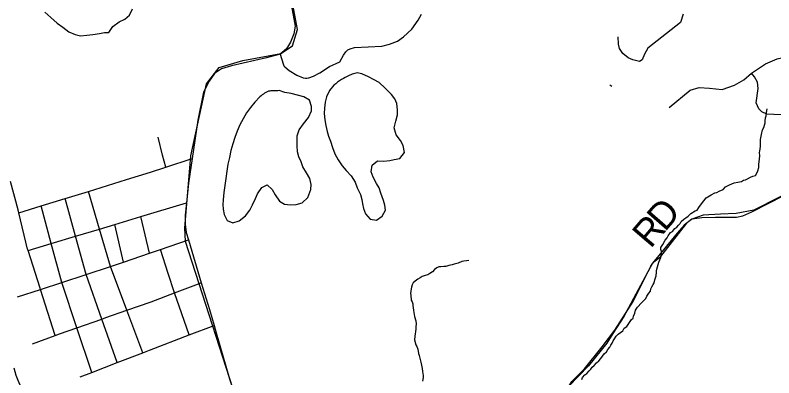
# Model space of a CAD drawing. Extents: x 0 to 34, y 0 to 22.
# Drawn here: x 2.523 to 3.323, y 15.477 to 15.86 of the extents above; entities that cross this region are included whole.
import ezdxf

# ---------------------------------------------------------------- set-up
doc = ezdxf.new("R2010")
doc.units = 0
for name, color, linetype in [('GM_X_City_Street', 7, 'Continuous'), ('GM_X_County_Road', 7, 'Continuous'), ('GM_X_County_Road_Text', 7, 'Continuous'), ('GM_X_Major_River', 7, 'Continuous'), ('GM_X_Minor_Lake', 7, 'Continuous'), ('GM_X_Minor_River', 7, 'Continuous'), ('GM_X_Rail_Line', 7, 'Continuous'), ('GM_X_Township_Road', 7, 'Continuous'), ('GM_X_US_Route', 7, 'Continuous')]:
    doc.layers.add(name, color=color, linetype=linetype)

msp = doc.modelspace()

# ---------------------------------------------------------------- linework, layer by layer
at = {"layer": 'GM_X_City_Street'}
for p, q in [((2.66455, 15.60886), (2.65535, 15.64744)), ((2.63694, 15.59946), (2.62776, 15.63911))]:
    msp.add_line(p, q, dxfattribs=at)
for points in [[(2.68156, 15.69953), (2.67833, 15.71215), (2.67348, 15.73109)], [(2.52675, 15.65143), (2.55011, 15.65857), (2.57554, 15.66634), (2.60022, 15.67389), (2.64032, 15.68642), (2.66539, 15.69425), (2.68156, 15.69953), (2.70934, 15.70857)], [(2.5649, 15.52203), (2.54956, 15.57061), (2.54918, 15.5718), (2.53648, 15.61153), (2.53597, 15.61313), (2.52675, 15.65143), (2.52598, 15.6546), (2.51791, 15.68449)], [(2.65747, 15.50379), (2.64059, 15.54861), (2.62319, 15.59479), (2.61173, 15.63427), (2.60022, 15.67389)], [(2.63037, 15.49334), (2.61415, 15.53936), (2.59758, 15.58638), (2.58649, 15.62664), (2.57554, 15.66634)], [(2.53648, 15.61153), (2.56082, 15.61888), (2.58649, 15.62664), (2.61173, 15.63427), (2.62776, 15.63911), (2.65535, 15.64744), (2.70346, 15.66198)], [(2.60372, 15.48307), (2.5879, 15.53018), (2.57187, 15.57794), (2.56082, 15.61888), (2.55011, 15.65857)], [(2.52537, 15.56267), (2.54956, 15.57061), (2.55046, 15.57091), (2.57187, 15.57794), (2.59758, 15.58638), (2.62319, 15.59479), (2.63694, 15.59946), (2.66455, 15.60886), (2.676, 15.61275), (2.70543, 15.62276)], [(2.7064, 15.52255), (2.69073, 15.56686), (2.68409, 15.58753), (2.676, 15.61275)], [(2.54111, 15.51316), (2.5649, 15.52203), (2.56949, 15.52373), (2.5879, 15.53018), (2.61415, 15.53936), (2.61832, 15.54082), (2.64059, 15.54861), (2.6662, 15.55757), (2.69073, 15.56686), (2.7191, 15.5776)], [(2.59135, 15.4783), (2.60372, 15.48307), (2.63037, 15.49334), (2.65747, 15.50379), (2.6643, 15.50642), (2.7064, 15.52255), (2.7325, 15.53255)]]:
    msp.add_lwpolyline(points, dxfattribs=at)
at = {"layer": 'GM_X_County_Road'}
for points in [[(2.80226, 15.81868), (2.80525, 15.80862), (2.80625, 15.8064), (2.80731, 15.80516), (2.81159, 15.80161), (2.81975, 15.79643), (2.82633, 15.79387), (2.82901, 15.79355), (2.8305, 15.79352), (2.8324, 15.79378), (2.83734, 15.79542), (2.84421, 15.79892), (2.85416, 15.80559), (2.86522, 15.81074), (2.86892, 15.8177), (2.87148, 15.82118), (2.87375, 15.82332), (2.87588, 15.82445), (2.88059, 15.82568), (2.90959, 15.82715), (2.91739, 15.82912), (2.92596, 15.8324), (2.93246, 15.83704), (2.9411, 15.84507), (2.94779, 15.85468), (2.9511, 15.8608)], [(3.01015, 15.37328), (3.01126, 15.3743), (3.02228, 15.38409), (3.08942, 15.44382), (3.09512, 15.45085), (3.10361, 15.46292), (3.10979, 15.47334), (3.12306, 15.48697), (3.14191, 15.5101), (3.1553, 15.52771), (3.17436, 15.55784), (3.19325, 15.59517), (3.19641, 15.59962), (3.20358, 15.60529), (3.21361, 15.61787), (3.23092, 15.64029), (3.23367, 15.64299), (3.23674, 15.64485), (3.24682, 15.64627), (3.26123, 15.6468), (3.28338, 15.64672), (3.29024, 15.64823), (3.29964, 15.65231), (3.36693, 15.68691)]]:
    msp.add_lwpolyline(points, dxfattribs=at)
at = {"layer": 'GM_X_Major_River'}
for points in [[(2.55404, 15.86283), (2.56036, 15.8572), (2.56706, 15.85156), (2.57303, 15.84707), (2.57937, 15.8422), (2.58594, 15.83941), (2.5916, 15.83815), (2.59823, 15.83859), (2.60469, 15.83941), (2.61191, 15.84059), (2.61685, 15.84163), (2.62158, 15.84172), (2.62568, 15.84771), (2.63241, 15.85289), (2.63834, 15.85562), (2.64353, 15.85969), (2.64651, 15.86665)], [(2.57421, 15.3616), (2.5689, 15.37081), (2.56618, 15.37637), (2.56271, 15.3827), (2.5611, 15.38748), (2.55855, 15.39265), (2.5562, 15.39821), (2.55311, 15.40434), (2.54982, 15.41029), (2.54766, 15.41603), (2.54606, 15.4208), (2.54393, 15.42787), (2.54234, 15.43359), (2.5402, 15.44028), (2.53784, 15.44526), (2.53479, 15.45386), (2.53154, 15.46133), (2.52612, 15.47434), (2.52377, 15.47989), (2.52165, 15.48734)]]:
    msp.add_lwpolyline(points, dxfattribs=at)
at = {"layer": 'GM_X_Minor_Lake'}
for points in [[(2.85893, 15.78593), (2.85429, 15.78031), (2.85095, 15.77354), (2.84954, 15.76806), (2.84887, 15.76181), (2.84858, 15.75594), (2.84923, 15.74929), (2.85028, 15.74358), (2.8517, 15.7371), (2.85313, 15.73215), (2.85514, 15.72681), (2.85731, 15.72032), (2.86005, 15.71364), (2.86336, 15.70713), (2.86762, 15.70081), (2.87191, 15.69599), (2.87694, 15.69041), (2.8812, 15.6837), (2.88357, 15.67759), (2.88688, 15.67071), (2.8885, 15.66556), (2.889, 15.66081), (2.89005, 15.65586), (2.89205, 15.65033), (2.89709, 15.64475), (2.90371, 15.64369), (2.90966, 15.64777), (2.91318, 15.65416), (2.91251, 15.65949), (2.91126, 15.66444), (2.90834, 15.67207), (2.90653, 15.6776), (2.90376, 15.68239), (2.90026, 15.6889), (2.89808, 15.69462), (2.89933, 15.70162), (2.90491, 15.70627), (2.91135, 15.70579), (2.91782, 15.70663), (2.92258, 15.70769), (2.92829, 15.70874), (2.93332, 15.71492), (2.93193, 15.72253), (2.92916, 15.7275), (2.9247, 15.73365), (2.92235, 15.74089), (2.92436, 15.74788), (2.92599, 15.75468), (2.92608, 15.75999), (2.92523, 15.76665), (2.92303, 15.77142), (2.9197, 15.77622), (2.91297, 15.78297), (2.90661, 15.78876), (2.90078, 15.79208), (2.89551, 15.79482), (2.88835, 15.79797), (2.88343, 15.799), (2.87829, 15.79757)], [(2.74199, 15.66509), (2.74191, 15.66016), (2.74202, 15.65522), (2.74325, 15.64951), (2.74638, 15.6432), (2.75241, 15.64083), (2.75909, 15.643), (2.76562, 15.64801), (2.77008, 15.65401), (2.77302, 15.65984), (2.77617, 15.66662), (2.77834, 15.67152), (2.78281, 15.67809), (2.78836, 15.68103), (2.79397, 15.67601), (2.79691, 15.67027), (2.80155, 15.66356), (2.80682, 15.66044), (2.81326, 15.65995), (2.81896, 15.66024), (2.82544, 15.66203), (2.83141, 15.66763), (2.83458, 15.67611), (2.83486, 15.68123), (2.83363, 15.6877), (2.83012, 15.69344), (2.82624, 15.69996), (2.82423, 15.70511), (2.82185, 15.71046), (2.82042, 15.7158), (2.82014, 15.72187), (2.82003, 15.7268), (2.82012, 15.73249), (2.82231, 15.73891), (2.82678, 15.74529), (2.83201, 15.75203), (2.83515, 15.75881), (2.83542, 15.76355), (2.83325, 15.77003), (2.82704, 15.77374), (2.82062, 15.77555), (2.814, 15.77717), (2.80719, 15.77842), (2.80115, 15.78023)]]:
    msp.add_lwpolyline(points, dxfattribs=at)
for points in [[(2.87829, 15.79757), (2.87504, 15.7961), (2.867, 15.79206), (2.85893, 15.78593)], [(2.80115, 15.78023), (2.79602, 15.77993), (2.79127, 15.77982), (2.78092, 15.77354), (2.74199, 15.66509)]]:
    msp.add_spline(points, degree=3, dxfattribs=at)
at = {"layer": 'GM_X_Minor_River'}
for points in [[(3.15206, 15.78452), (3.14981, 15.78592)], [(3.30763, 15.70786), (3.30793, 15.71184), (3.30782, 15.7145), (3.30807, 15.71658), (3.3085, 15.71865), (3.30878, 15.72149), (3.30869, 15.72529), (3.3086, 15.7287), (3.30923, 15.73058), (3.3097, 15.73398), (3.31098, 15.73888), (3.3122, 15.7415), (3.31283, 15.74376), (3.31348, 15.74639), (3.31354, 15.74848), (3.314, 15.7515), (3.31463, 15.75357), (3.31492, 15.75698), (3.31536, 15.75924), (3.31561, 15.76113)], [(3.12026, 15.47563), (3.12108, 15.47769), (3.12363, 15.48065), (3.12576, 15.48191), (3.12812, 15.48469), (3.12988, 15.48653), (3.13108, 15.48858), (3.13322, 15.49023), (3.13577, 15.49299), (3.1383, 15.49519), (3.14028, 15.49779), (3.14384, 15.50262), (3.14636, 15.50463), (3.14758, 15.50725), (3.14993, 15.50983), (3.15075, 15.51189), (3.15233, 15.51393), (3.15354, 15.51617), (3.15493, 15.51859), (3.15653, 15.52139), (3.15868, 15.52341), (3.16101, 15.52505), (3.16354, 15.52706), (3.16513, 15.52967), (3.16766, 15.53149), (3.16904, 15.53353), (3.17062, 15.53557), (3.17261, 15.53874), (3.17456, 15.5402), (3.17481, 15.54228), (3.17604, 15.54565), (3.17689, 15.54866), (3.17907, 15.55201), (3.18319, 15.55625), (3.18593, 15.5592), (3.1877, 15.56105), (3.1889, 15.56329), (3.19089, 15.56664), (3.19267, 15.56886), (3.19293, 15.57132), (3.19431, 15.57318), (3.19553, 15.5758), (3.19672, 15.57766), (3.19738, 15.58067), (3.19801, 15.58274), (3.19864, 15.585), (3.19894, 15.58879), (3.19918, 15.59068), (3.20004, 15.59425), (3.20152, 15.59933), (3.20356, 15.6042), (3.20399, 15.60609), (3.20444, 15.60835), (3.2045, 15.61044), (3.20361, 15.61274), (3.20367, 15.61483), (3.20566, 15.6178), (3.20808, 15.62266), (3.21042, 15.62506), (3.21124, 15.62693), (3.21381, 15.63045), (3.21594, 15.63172), (3.2185, 15.63487), (3.22043, 15.63613), (3.2224, 15.63835), (3.22416, 15.6402), (3.22517, 15.64225), (3.2279, 15.64464), (3.23003, 15.64609), (3.23255, 15.64772), (3.23529, 15.65048), (3.23994, 15.65357), (3.24186, 15.65427), (3.24383, 15.65686), (3.24642, 15.66096), (3.24898, 15.66392), (3.25135, 15.66707), (3.25483, 15.66943), (3.25676, 15.67032), (3.26062, 15.67229), (3.26272, 15.6728), (3.26523, 15.67424), (3.26928, 15.67601), (3.27182, 15.67859), (3.27606, 15.68074), (3.28088, 15.68287), (3.2847, 15.6837), (3.28661, 15.68402), (3.28872, 15.68453), (3.29084, 15.68579), (3.29295, 15.6863), (3.29507, 15.68737), (3.29815, 15.68879), (3.30065, 15.68986), (3.30353, 15.69072), (3.30493, 15.69333), (3.30595, 15.69577), (3.307, 15.69915), (3.3071, 15.70256), (3.30763, 15.70786)], [(3.00124, 15.60106), (2.99857, 15.60076), (2.99589, 15.60028), (2.99379, 15.59996), (2.98995, 15.59837), (2.98554, 15.59718), (2.98362, 15.59666), (2.98018, 15.59582), (2.97692, 15.59478), (2.97482, 15.59466), (2.97159, 15.59456), (2.96949, 15.59425), (2.96756, 15.59336), (2.96485, 15.59154), (2.96269, 15.58914), (2.96017, 15.58732), (2.95785, 15.58606), (2.95498, 15.5852), (2.95191, 15.58416), (2.94997, 15.58289), (2.94746, 15.58145), (2.94473, 15.57925), (2.9426, 15.57761), (2.94159, 15.57555), (2.94075, 15.57292), (2.94032, 15.57104), (2.9398, 15.56631), (2.93994, 15.56441), (2.94036, 15.55927), (2.94145, 15.55734), (2.94196, 15.55524), (2.94229, 15.55333), (2.94242, 15.55143), (2.94271, 15.5482), (2.94405, 15.54189), (2.94544, 15.5373), (2.94554, 15.53426), (2.94546, 15.53123), (2.94521, 15.52915), (2.94493, 15.52593), (2.94467, 15.52366), (2.94422, 15.52121), (2.94392, 15.51742), (2.9453, 15.51226), (2.94638, 15.51032), (2.94725, 15.50745), (2.94807, 15.50287), (2.94896, 15.50076), (2.94999, 15.49674), (2.95067, 15.49388), (2.95133, 15.49063), (2.95199, 15.48701), (2.95248, 15.48414), (2.95312, 15.47976), (2.95306, 15.47768), (2.95238, 15.4739)]]:
    msp.add_lwpolyline(points, dxfattribs=at)
at = {"layer": 'GM_X_Rail_Line'}
for points in [[(2.87659, 15.24999), (2.8671, 15.25758), (2.85749, 15.27176), (2.77342, 15.40909), (2.76308, 15.43264), (2.70257, 15.6211), (2.70176, 15.63546), (2.70801, 15.71139), (2.72459, 15.78738), (2.73794, 15.8046), (2.76282, 15.81194), (2.80304, 15.81953), (2.81527, 15.82751), (2.82038, 15.84465), (2.81335, 15.88257), (2.80906, 15.90346), (2.80756, 15.942), (2.80049, 15.95221), (2.79436, 15.96217)], [(3.46486, 15.73695), (3.3018, 15.6543), (3.28321, 15.6507), (3.26667, 15.64983), (3.24842, 15.64895), (3.23641, 15.64467), (3.22814, 15.63834), (3.22082, 15.62989), (3.20633, 15.61243), (3.19489, 15.59833), (3.16446, 15.54198), (3.15319, 15.52395), (3.14657, 15.51394), (3.12727, 15.49014), (3.10623, 15.46804)]]:
    msp.add_lwpolyline(points, dxfattribs=at)
at = {"layer": 'GM_X_Township_Road'}
for points in [[(3.22721, 15.86081), (3.22432, 15.85205), (3.18976, 15.82509), (3.18639, 15.81854), (3.18405, 15.81264), (3.18111, 15.81092), (3.17409, 15.8127), (3.16915, 15.81478), (3.16365, 15.81942), (3.16005, 15.82457), (3.15902, 15.82938), (3.15867, 15.83711)], [(3.21258, 15.76257), (3.23444, 15.78069), (3.24391, 15.78341), (3.25489, 15.78281), (3.26814, 15.78158), (3.2814, 15.786), (3.29122, 15.79165), (3.29938, 15.79872), (3.3141, 15.80857), (3.32645, 15.81381), (3.33543, 15.81605), (3.3459, 15.81787), (3.35514, 15.81855), (3.36789, 15.81701), (3.37871, 15.81581)], [(3.3364, 15.75482), (3.32289, 15.75507), (3.31528, 15.75532), (3.31005, 15.75771), (3.307, 15.76087), (3.30425, 15.76753), (3.30611, 15.78263), (3.30559, 15.78916), (3.30233, 15.79483), (3.29938, 15.79872)]]:
    msp.add_lwpolyline(points, dxfattribs=at)
at = {"layer": 'GM_X_US_Route'}
for points in [[(2.8135, 15.87328), (2.81811, 15.84821), (2.81682, 15.84028), (2.81322, 15.83132), (2.80895, 15.82447), (2.80226, 15.81868), (2.7877, 15.81492), (2.75076, 15.80622), (2.74021, 15.80325), (2.73299, 15.79824), (2.72752, 15.79011), (2.72135, 15.7786), (2.71535, 15.74903), (2.70934, 15.70857), (2.70551, 15.68279), (2.70346, 15.66198), (2.70216, 15.64875), (2.70196, 15.63945), (2.70309, 15.63048), (2.70543, 15.62276), (2.7191, 15.5776), (2.72766, 15.54931), (2.7325, 15.53255)], [(2.7325, 15.53255), (2.73479, 15.52464), (2.74894, 15.47633), (2.75287, 15.46412), (2.76012, 15.44162), (2.76488, 15.42678), (2.76776, 15.42162), (2.76914, 15.41875)]]:
    msp.add_lwpolyline(points, dxfattribs=at)

# ---------------------------------------------------------------- texts
at = {"layer": 'GM_X_County_Road_Text'}
for s, rotation, p in [('D', 48.99569, (3.20793, 15.63058)), ('R', 49.45056, (3.1928, 15.61289))]:
    msp.add_text(s, height=0.02841, rotation=rotation, dxfattribs=at).set_placement(p)

doc.saveas('drawing.dxf')
